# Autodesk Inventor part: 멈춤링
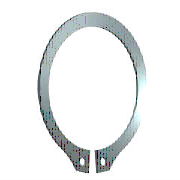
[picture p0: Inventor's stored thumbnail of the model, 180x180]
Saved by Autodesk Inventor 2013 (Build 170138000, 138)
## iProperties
IsCustomPart: 1
Created: 2012-02
Part Number: 멈춤링
Material: 강철, 연강
Description: 리테이닝 링(C형)
Document SubType Name: Modeling
Standard: KS B 1336
Designer: mduedu
Standards Organization: KS
Language: ko-KR
Size Designation: 20 x 1.2
Categories: <MemberInstance><Categories><Category DisplayName="샤프트 부품" InternalName="7f7aeb1f-a693-4053-b835-cee3144e0d98" Mnemonic="SHFT"><Category DisplayName="써클립" Inter
Density: 1 g/cm^3
Author: mduedu
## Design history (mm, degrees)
sketch "스케치1"
  geometry: L1 (-6, 0)-(6, 0) reference; L2 (0, 20.189)-(0, -80.536) reference; L3 (-48.09, 0)-(48.09, 0) reference; L4 (-0.5, -19.487)-(-0.5, -23.387); L5 (-0.5, -6.54)-(-0.5, -13.29); L6 (-2.795, 2.7)-(3.672, 2.7); L7 (0.5, -6.54)-(0.5, -13.29); L8 (0.5, -19.487)-(0.5, -23.387); C1 r 1 at (-2, -21.219); C2 r 1 at (2, -21.219); A1 r 9.5 centre (0, -10) between (0.5, -19.487) and (-0.5, -19.487); A2 r 12.025 centre (0, -9.325) between (5.071, -20.228) and (-5.071, -20.228); A3 r 13.396 centre (0, -10) between (-2.351, -23.188) and (-0.5, -23.387); A4 r 2 centre (-2, -21.219) between (-3.957, -21.631) and (-2.351, -23.188); A5 r 2 centre (-5.915, -22.042) between (-3.957, -21.631) and (-5.071, -20.228); A6 r 2 centre (5.915, -22.042) between (5.071, -20.228) and (3.957, -21.631); A7 r 2 centre (2, -21.219) between (2.351, -23.188) and (3.957, -21.631); A8 r 13.396 centre (0, -10) between (0.5, -23.387) and (2.351, -23.188)
  constraints: 16 point on circle, 12 end point, 10 centre point, 9 symmetric about line, 5 point on line, 4 tangent, 3 coincident, 2 horizontal, 1 perpendicular, 1 vertical, 5 other
  dimensions: "d0" = 19 diameter of A1 (= ND); "d1" = 3.9 distance of L4.end L4.start (= SRB2); "d6" = 0.5 distance between parallel lines of L2 L5 (= 0.25 x SD5); "d7" = 2.7 distance between parallel lines of L6 L3 (= SRB1); "d8" = 0.675 distance of A1.centre A2.centre (= 0.25 x SRB1); "d9" = 2 radius of A4 (= SD5); "d10" = 2 radius of A5 (= SD5); "d11" = 1.5 distance from line of L4 A4.centre (= 0.75 x SD5); "d12" = 2 diameter of C1 (= SD5); "d13" = 2 diameter of C2 (= SD5); "d14" = 10 distance from line of A1.centre L1 (= 0.5 x WD)
extrude "본체" new body sketch "스케치1" distance "d2" = 1.2 (= SD); taper "d3" = 0 deg
workaxis "Work Axis1"
workplane "Work Plane1"
body "Solid1"
other parameters: "SD" = 1.2 [user parameter; used in 1 equation term], "SRB1" = 2.7 [user parameter; used in 2 equation terms], "ND" = 19 [user parameter; used in 1 equation term], "SRB2" = 3.9 [user parameter; used in 1 equation term], "SD5" = 2 [user parameter; used in 6 equation terms], "d15" = 0, "d16" = 0, "d17" = 0, "d41" = 0, "d42" = 0, "SD3" = 18.5 [user parameter], "WDMAX" = 21 [user parameter]
